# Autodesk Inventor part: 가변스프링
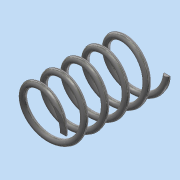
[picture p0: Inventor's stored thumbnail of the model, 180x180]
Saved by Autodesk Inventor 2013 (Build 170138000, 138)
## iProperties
Created: 2017-02
Part Number: 가변스프링
Material: 강철, 탄소
Document SubType Name: Modeling
Designer: dgall
Density: 7.87 g/cm^3
Mass: 6.5131 g
Surface Area: 16.8031 cm^2
Volume: 0.827586 cm^3
Author: dgall
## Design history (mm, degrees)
sketch "스케치1"
  geometry: L1 (0, 0)-(0, 35); L2 (0, 0)-(8.5, 0); L3 (0, 35)-(8.5, 35); C1 r 1 at (8.5, 0)
  constraints: 6 end point, 1 centre point, 1 coincident, 1 parallel, 1 perpendicular, 1 vertical, 1 vertical alignment
  dimensions: "d0" = 35 distance of L1.start L1.end (derived); "d1" = 2 diameter of C1; "d2" = 17 diameter of L2.end L1
feature "코일1" sketch "스케치1" pitch "d3" = 10; turns "d5" = 5; dims "d4" = 35 (= d0), "d6" = 0, angle "d7" = 90 deg, angle "d8" = 90 deg, "d9" = 0, "d10" = 0
node "작업 평면1"
node "작업 평면2"
feature "분할1"
feature "분할2"
node "솔리드1"
other parameters: "d11" = 0, "d12" = 0
